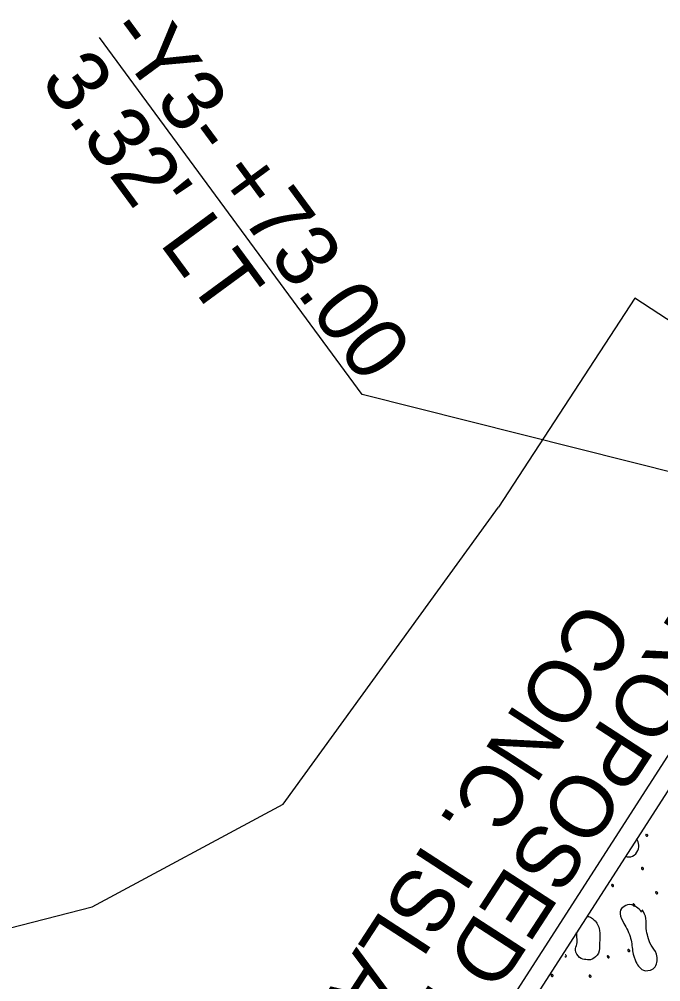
# Model space of a CAD drawing. Extents: x 1763480 to 1764420, y 711010 to 712012.
# Drawn here: x 1763854.99 to 1763880.68, y 711480.44 to 711519 of the extents above; entities that cross this region are included whole.
import ezdxf

# ---------------------------------------------------------------- set-up
doc = ezdxf.new("R2010")
doc.units = 0
for name, color, linetype in [('Old_Level_10', 7, 'Continuous'), ('Prop Conc Island Cover', 7, 'Continuous'), ('Prop EOT', 7, 'Continuous'), ('Prop Grid Mask', 7, 'Continuous'), ('Prop Lane Lines', 7, 'Continuous')]:
    doc.layers.add(name, color=color, linetype=linetype)

msp = doc.modelspace()

# ---------------------------------------------------------------- linework, layer by layer
at = {"layer": 'Old_Level_10'}
for points in [[(1763880.103, 711486.354), (1763880.077, 711486.355), (1763880.075, 711486.277), (1763880.152, 711486.25), (1763880.174, 711486.31), (1763880.139, 711486.333), (1763880.116, 711486.342), (1763880.104, 711486.345)], [(1763879.281, 711485.474), (1763879.353, 711485.421), (1763879.562, 711485.439), (1763879.807, 711485.678), (1763879.806, 711485.998), (1763879.737, 711486.13), (1763879.721, 711486.16)], [(1763879.932, 711485.029), (1763879.905, 711485.029), (1763879.901, 711484.952), (1763879.981, 711484.922), (1763880.001, 711484.985), (1763879.966, 711485.008), (1763879.943, 711485.017), (1763879.931, 711485.02)], [(1763878.735, 711484.341), (1763878.708, 711484.341), (1763878.703, 711484.263), (1763878.784, 711484.235), (1763878.804, 711484.298), (1763878.769, 711484.32), (1763878.747, 711484.33), (1763878.734, 711484.334)], [(1763880.497, 711484.051), (1763880.471, 711484.051), (1763880.468, 711483.975), (1763880.547, 711483.946), (1763880.568, 711484.005), (1763880.533, 711484.031), (1763880.509, 711484.04), (1763880.496, 711484.043)], [(1763879.928, 711483.231), (1763879.779, 711483.396), (1763879.503, 711483.581), (1763879.198, 711483.469), (1763879.001, 711483.275), (1763879.125, 711482.875), (1763879.517, 711482.251), (1763879.529, 711481.658), (1763879.696, 711481.176), (1763879.807, 711481.03), (1763880.022, 711480.822), (1763880.531, 711480.957), (1763880.565, 711481.591), (1763880.256, 711481.901), (1763880.171, 711482.254), (1763880.073, 711482.546), (1763880.13, 711482.986), (1763880.008, 711483.21), (1763879.936, 711483.315)], [(1763879.583, 711483.561), (1763879.557, 711483.561), (1763879.554, 711483.486), (1763879.632, 711483.454), (1763879.653, 711483.518), (1763879.617, 711483.54), (1763879.594, 711483.549), (1763879.582, 711483.553)], [(1763877.721, 711483.047), (1763877.811, 711483.064), (1763878.033, 711482.955), (1763878.286, 711482.525), (1763878.208, 711481.959), (1763878.248, 711481.564), (1763877.911, 711481.286), (1763877.692, 711481.323), (1763877.424, 711481.359), (1763877.198, 711481.722), (1763877.35, 711481.931), (1763877.323, 711482.235), (1763877.317, 711482.32), (1763877.308, 711482.404)], [(1763879.383, 711481.737), (1763879.357, 711481.738), (1763879.352, 711481.66), (1763879.433, 711481.63), (1763879.453, 711481.693), (1763879.418, 711481.716), (1763879.395, 711481.726), (1763879.383, 711481.73)], [(1763876.84, 711481.455), (1763876.841, 711481.454), (1763876.851, 711481.439), (1763876.892, 711481.421), (1763876.908, 711481.485), (1763876.876, 711481.507), (1763876.856, 711481.515), (1763876.847, 711481.518)], [(1763878.557, 711481.488), (1763878.53, 711481.489), (1763878.529, 711481.412), (1763878.607, 711481.383), (1763878.627, 711481.443), (1763878.592, 711481.468), (1763878.569, 711481.477), (1763878.557, 711481.481)], [(1763876.31, 711480.741), (1763876.283, 711480.742), (1763876.281, 711480.664), (1763876.36, 711480.635), (1763876.38, 711480.698), (1763876.344, 711480.72), (1763876.321, 711480.729), (1763876.309, 711480.733)], [(1763877.83, 711480.712), (1763877.804, 711480.712), (1763877.801, 711480.634), (1763877.879, 711480.607), (1763877.901, 711480.668), (1763877.865, 711480.691), (1763877.842, 711480.7), (1763877.829, 711480.703)]]:
    msp.add_open_spline(points, degree=3, dxfattribs=at)
at = {"layer": 'Prop Conc Island Cover'}
msp.add_line((1763888.402, 711499.672), (1763863.551, 711460.991), dxfattribs=at)
at = {"layer": 'Prop EOT'}
for p, q in [((1763879.643, 711507.829), (1763874.178, 711499.454)), ((1763907.848, 711489.337), (1763879.643, 711507.829)), ((1763865.559, 711487.555), (1763874.178, 711499.454)), ((1763857.913, 711483.432), (1763865.559, 711487.555)), ((1763853.71, 711482.36), (1763857.913, 711483.432))]:
    msp.add_line(p, q, dxfattribs=at)
at = {"layer": 'Prop Grid Mask'}
for p, q in [((1763868.724, 711503.961), (1763858.206, 711518.266)), ((1763890.085, 711498.591), (1763868.724, 711503.961))]:
    msp.add_line(p, q, dxfattribs=at)
at = {"layer": 'Prop Lane Lines'}
msp.add_line((1763862.92, 711461.396), (1763888.866, 711501.781), dxfattribs=at)

# ---------------------------------------------------------------- texts
at = {"layer": 'Prop Grid Mask'}
for s, rotation, p in [('-Y3- +73.00', 306.325, (1763858.405, 711518.467)), ("3.32' LT", 306.325, (1763855.786, 711516.542)), ('PROPOSED MONO.', 236.9842, (1763882.337, 711497.181)), ('CONC. ISLAND', 236.9842, (1763877.603, 711495.87))]:
    msp.add_text(s, height=2.5, rotation=rotation, dxfattribs=at).set_placement(p)

doc.saveas('drawing.dxf')
